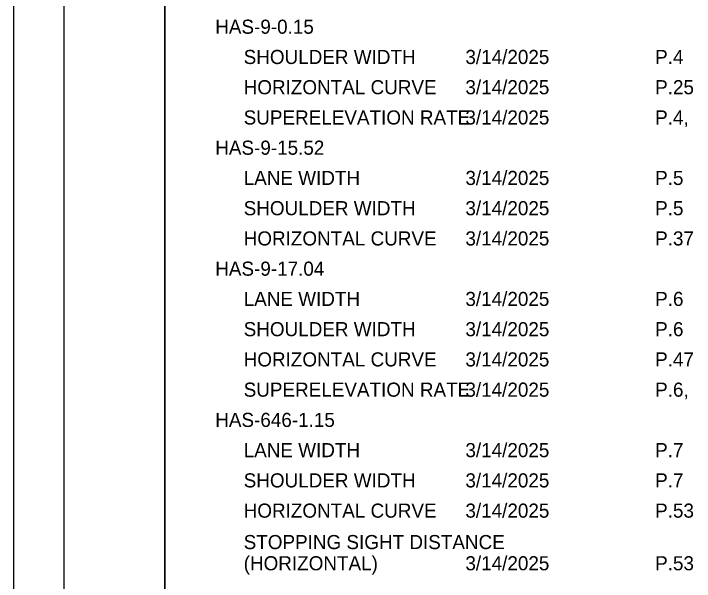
# Model space of a CAD drawing. Extents: x 0 to 34, y -32.5 to 22.
# Drawn here: x 0 to 6.75, y 5.35 to 10.98 of the extents above; entities that cross this region are included whole.
import ezdxf

# ---------------------------------------------------------------- set-up
doc = ezdxf.new("R2010")
doc.units = 0
for name, color, linetype in [('GM_X_Adjacent_County', 7, 'Continuous'), ('GM_X_County', 7, 'Continuous'), ('GM_X_Section', 7, 'Continuous')]:
    doc.layers.add(name, color=color, linetype=linetype)

msp = doc.modelspace()

# ---------------------------------------------------------------- linework, layer by layer
at = {"layer": 'GM_X_County'}
for points in [[(0.5, 21.5), (1.5, 21.5), (1.5, 0.5), (0.5, 0.5)], [(1.5, 21.5), (33.5, 21.5), (33.5, 0.5), (1.5, 0.5)]]:
    msp.add_lwpolyline(points, close=True, dxfattribs=at)
at = {"layer": 'GM_X_Section'}
msp.add_lwpolyline([(0, 0), (34, 0), (34, 22), (0, 22)], close=True, dxfattribs=at)

# ---------------------------------------------------------------- texts
at = {"layer": 'GM_X_Adjacent_County'}
for s, p in [('HAS-9-0.15', (2, 10.7843)), ('SHOULDER WIDTH', (2.2821, 10.4843)), ('3/14/2025', (4.4815, 10.4843)), ('P.4', (6.3635, 10.4843)), ('HORIZONTAL CURVE', (2.2821, 10.1843)), ('3/14/2025', (4.4815, 10.1843)), ('P.25', (6.3635, 10.1843)), ('SUPERELEVATION RATE', (2.2821, 9.8843)), ('3/14/2025', (4.4815, 9.8843)), ('P.4', (6.3635, 9.8843)), (', ', (6.6449, 9.8843)), ('HAS-9-15.52', (2, 9.5843)), ('LANE WIDTH', (2.2821, 9.2843)), ('3/14/2025', (4.4815, 9.2843)), ('P.5', (6.3635, 9.2843)), ('SHOULDER WIDTH', (2.2821, 8.9843)), ('3/14/2025', (4.4815, 8.9843)), ('P.5', (6.3635, 8.9843)), ('HORIZONTAL CURVE', (2.2821, 8.6843)), ('3/14/2025', (4.4815, 8.6843)), ('P.37', (6.3635, 8.6843)), ('HAS-9-17.04', (2, 8.3843)), ('LANE WIDTH', (2.2821, 8.0843)), ('3/14/2025', (4.4815, 8.0843)), ('P.6', (6.3635, 8.0843)), ('SHOULDER WIDTH', (2.2821, 7.7843)), ('3/14/2025', (4.4815, 7.7843)), ('P.6', (6.3635, 7.7843)), ('3/14/2025', (4.4815, 7.4843)), ('HORIZONTAL CURVE', (2.2821, 7.4843)), ('P.47', (6.3635, 7.4843)), ('SUPERELEVATION RATE', (2.2821, 7.1843)), ('3/14/2025', (4.4815, 7.1843)), ('P.6', (6.3635, 7.1843)), (', ', (6.6449, 7.1843)), ('HAS-646-1.15', (2, 6.8843)), ('LANE WIDTH', (2.2821, 6.5843)), ('3/14/2025', (4.4815, 6.5843)), ('P.7', (6.3635, 6.5843)), ('SHOULDER WIDTH', (2.2821, 6.2843)), ('3/14/2025', (4.4815, 6.2843)), ('P.7', (6.3635, 6.2843)), ('HORIZONTAL CURVE', (2.2821, 5.9843)), ('3/14/2025', (4.4815, 5.9843)), ('P.53', (6.3635, 5.9843)), ('STOPPING SIGHT DISTANCE', (2.2821, 5.6723)), ('(HORIZONTAL)', (2.2821, 5.4623)), ('3/14/2025', (4.4815, 5.4623)), ('P.53', (6.3635, 5.4623))]:
    msp.add_text(s, height=0.14, dxfattribs=at).set_placement(p)

doc.saveas('drawing.dxf')
